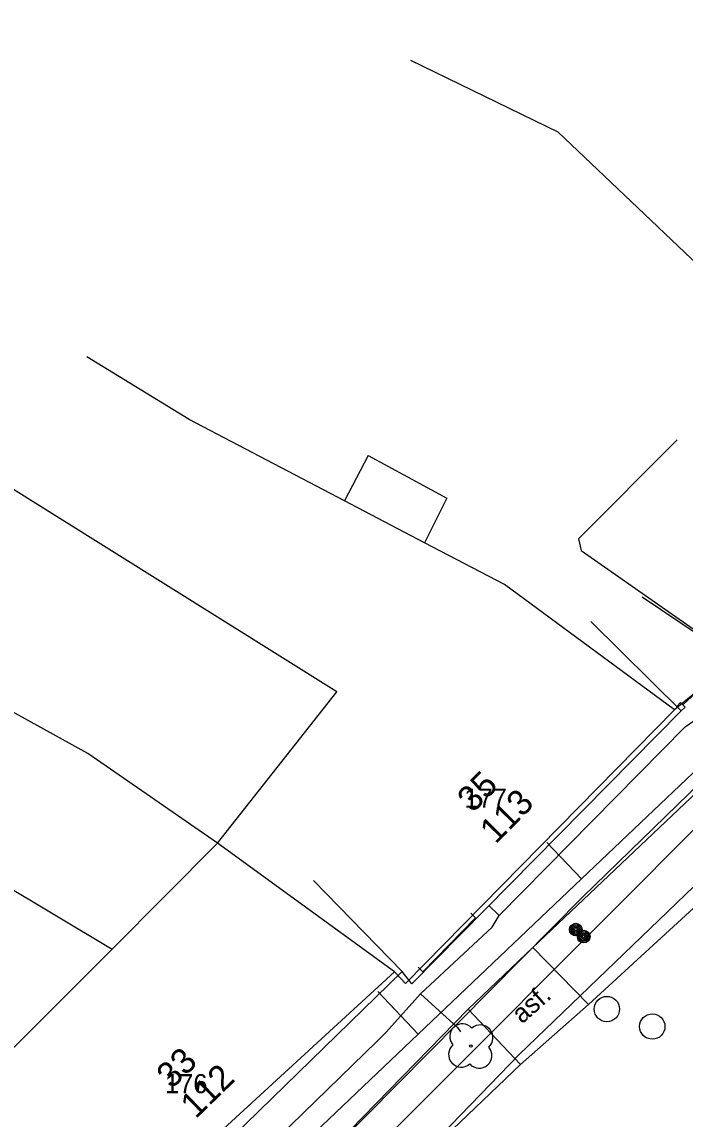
# Model space of a CAD drawing. Extents: x -601580 to 4, y -1204314 to 4.
# Drawn here: x -600403.88 to -600377.73, y -1203632.11 to -1203588.88 of the extents above; entities that cross this region are included whole.
import ezdxf

# ---------------------------------------------------------------- set-up
doc = ezdxf.new("R2010")
doc.units = 0
for name, color, linetype in [('00-INNOGY-NTL', 7, 'Continuous'), ('00-KN-HRANICE PARCEL', 7, 'Continuous'), ('00-KN-PARC. CISLA', 7, 'Continuous'), ('00-KN-VNITRNI KRESBA', 7, 'Continuous'), ('00-POLOHOPIS', 7, 'Continuous'), ('00-SITE KOM. KABEL', 7, 'Continuous'), ('00-VAK-VODA-RAD IGIS', 7, 'Continuous'), ('Vrstva 22', 7, 'Continuous'), ('Vrstva 25', 7, 'Continuous'), ('Vrstva 27', 7, 'Continuous'), ('Vrstva 6', 7, 'Continuous')]:
    doc.layers.add(name, color=color, linetype=linetype)

# ---------------------------------------------------------------- blocks, each defined once
blk = doc.blocks.new('6.01A_56')
at = {"layer": 'Vrstva 25'}
for radius in [0.25, 0.2, 0.15, 0.1, 0.05]:
    blk.add_circle((0, 0), radius, dxfattribs=at)
blk = doc.blocks.new('6.01A_58')
at = {"layer": 'Vrstva 25'}
for radius in [0.25, 0.2, 0.15, 0.1, 0.05]:
    blk.add_circle((0, 0), radius, dxfattribs=at)
blk = doc.blocks.new('6.01A_60')
at = {"layer": 'Vrstva 25'}
for radius in [0.25, 0.2, 0.15, 0.1, 0.05]:
    blk.add_circle((0, 0), radius, dxfattribs=at)
blk = doc.blocks.new('6.01A_62')
at = {"layer": 'Vrstva 25'}
for radius in [0.25, 0.2, 0.15, 0.1, 0.05]:
    blk.add_circle((0, 0), radius, dxfattribs=at)
blk = doc.blocks.new('6.20_272')
at = {"layer": 'Vrstva 27'}
blk.add_circle((0, 0), 0.5, dxfattribs=at)
blk = doc.blocks.new('6.20_274')
at = {"layer": 'Vrstva 27'}
blk.add_circle((0, 0), 0.5, dxfattribs=at)
blk = doc.blocks.new('3.13_710')
at = {"layer": 'Vrstva 22'}
blk.add_circle((0, 0), 0.05, dxfattribs=at)
for centre, start, end in [((0, 0.5), 359.9999, 179.9999), ((-0.5, 0), 89.9999, 269.9999), ((0.5, 0), 269.9999, 89.9999), ((0, -0.5), 179.9999, 359.9999)]:
    blk.add_arc(centre, 0.5, start, end, dxfattribs=at)
blk = doc.blocks.new('VCHOD_470')
at = {"layer": 'Vrstva 6'}
blk.add_line((0, 0.25), (0, 0), dxfattribs=at)
blk = doc.blocks.new('VCHOD_472')
at = {"layer": 'Vrstva 6'}
blk.add_line((0, 0.25), (0, 0), dxfattribs=at)

msp = doc.modelspace()

# ---------------------------------------------------------------- linework, layer by layer
at = {"layer": '00-INNOGY-NTL'}
for p, q in [((-600383.18, -1203621.21), (-600381.81, -1203622.65)), ((-600389.85, -1203627.09), (-600388.25, -1203628.77))]:
    msp.add_line(p, q, dxfattribs=at)
msp.add_lwpolyline([(-600244.39, -1203507.91), (-600260.95, -1203522.7), (-600267.65, -1203528.68), (-600275.18, -1203535.41), (-600281.02, -1203540.17), (-600295.58, -1203552.03), (-600296.1, -1203552.46), (-600320.53, -1203575.02), (-600330.42, -1203584.14), (-600331.17, -1203584.64), (-600349.13, -1203596.9), (-600357.35, -1203602.5), (-600360.96, -1203604.97), (-600363.47, -1203606.94), (-600365.34, -1203608.52), (-600370.83, -1203612.98), (-600376.39, -1203617.5), (-600381.81, -1203622.65), (-600388.25, -1203628.77), (-600399.65, -1203639.6)], dxfattribs=at)
at = {"layer": '00-KN-HRANICE PARCEL'}
for p, q in [((-600378.15, -1203615.98), (-600384.85, -1203611.05)), ((-600375.72, -1203613.98), (-600378.15, -1203615.98)), ((-600400.8, -1203636.96), (-600389.19, -1203626.31))]:
    msp.add_line(p, q, dxfattribs=at)
for points in [[(-600468.32, -1203708.8), (-600459.02, -1203700.91), (-600447.7, -1203689.53), (-600417.71, -1203659.51), (-600398.8, -1203640.57), (-600381.76, -1203623.36), (-600376.64, -1203618.38), (-600366.85, -1203610.56), (-600358.79, -1203604.64), (-600335.27, -1203586.75), (-600326.92, -1203580.15), (-600315.47, -1203571.41), (-600313.87, -1203569.96), (-600309.19, -1203565.44), (-600307.64, -1203563.87), (-600297.75, -1203553.71), (-600294.09, -1203550.64), (-600277.89, -1203537.3), (-600263.22, -1203524.94), (-600248.8, -1203512.9), (-600231.21, -1203497.85)], [(-600468.32, -1203708.8), (-600459.02, -1203700.91), (-600447.7, -1203689.53), (-600417.71, -1203659.51), (-600398.8, -1203640.57), (-600381.76, -1203623.36), (-600376.64, -1203618.38), (-600366.85, -1203610.56), (-600358.79, -1203604.64), (-600335.27, -1203586.75), (-600326.92, -1203580.15), (-600315.47, -1203571.41), (-600313.87, -1203569.96), (-600309.19, -1203565.44), (-600307.64, -1203563.87), (-600297.75, -1203553.71), (-600294.09, -1203550.64), (-600277.89, -1203537.3), (-600263.22, -1203524.94), (-600248.8, -1203512.9), (-600231.21, -1203497.85)], [(-600388.55, -1203590.38), (-600382.75, -1203593.21), (-600374.59, -1203600.96), (-600367.79, -1203607.52)], [(-600384.85, -1203611.05), (-600388.01, -1203609.4), (-600391.16, -1203607.75), (-600397.28, -1203604.55), (-600401.32, -1203602.08)], [(-600389.19, -1203626.31), (-600396.16, -1203621.24), (-600401.28, -1203617.71), (-600406.61, -1203614.77), (-600412.28, -1203611.63), (-600415.64, -1203609.77), (-600419.57, -1203607.57), (-600421.24, -1203606.59)], [(-600389.19, -1203626.31), (-600388.76, -1203626.77), (-600378.15, -1203615.98)]]:
    msp.add_lwpolyline(points, dxfattribs=at)
at = {"layer": '00-KN-VNITRNI KRESBA'}
for p, q in [((-600391.46, -1203615.28), (-600411.2, -1203602.94)), ((-600378.04, -1203605.35), (-600381.93, -1203609.25)), ((-600390.22, -1203605.96), (-600391.16, -1203607.75)), ((-600390.22, -1203605.96), (-600387.12, -1203607.65)), ((-600387.12, -1203607.65), (-600388.01, -1203609.4)), ((-600381.93, -1203609.25), (-600381.83, -1203609.71)), ((-600381.83, -1203609.71), (-600375.72, -1203613.98)), ((-600396.16, -1203621.24), (-600391.46, -1203615.28)), ((-600416.33, -1203615.85), (-600400.32, -1203625.42)), ((-600400.32, -1203625.42), (-600396.16, -1203621.24)), ((-600406.75, -1203631.83), (-600400.32, -1203625.42))]:
    msp.add_line(p, q, dxfattribs=at)
at = {"layer": '00-POLOHOPIS'}
for p, q in [((-600376.03, -1203614.125), (-600377.819, -1203615.79)), ((-600383.729, -1203625.347), (-600375.979, -1203617.997)), ((-600371.979, -1203618.807), (-600381.54, -1203627.597)), ((-600388.073, -1203626.304), (-600385.997, -1203624.176)), ((-600386.289, -1203627.775), (-600383.729, -1203625.347)), ((-600383.729, -1203625.347), (-600381.54, -1203627.597)), ((-600386.289, -1203627.775), (-600394.949, -1203636.66)), ((-600386.289, -1203627.775), (-600384.217, -1203629.96)), ((-600381.54, -1203627.597), (-600384.217, -1203629.96)), ((-600393.183, -1203638.488), (-600384.217, -1203629.96))]:
    msp.add_line(p, q, dxfattribs=at)
for points in [[(-600370.84, -1203603.844), (-600367.516, -1203607.579), (-600367.267, -1203607.978), (-600375.167, -1203614.412), (-600379.427, -1203611.552)], [(-600381.443, -1203612.511), (-600377.885, -1203616.024), (-600388.504, -1203626.779), (-600388.886, -1203626.29)], [(-600377.885, -1203616.024), (-600377.734, -1203615.878), (-600377.908, -1203615.698), (-600378.063, -1203615.848)], [(-600392.376, -1203622.709), (-600388.886, -1203626.29), (-600400.189, -1203637.306), (-600400.532, -1203636.909), (-600403.801, -1203633.126)]]:
    msp.add_lwpolyline(points, dxfattribs=at)
at = {"layer": '00-SITE KOM. KABEL'}
for points in [[(-600385.06, -1203624.09), (-600377.73, -1203616.65), (-600374.7, -1203614.56), (-600371.93, -1203612.56)], [(-600385.06, -1203624.09), (-600385.47, -1203623.7)], [(-600388.16, -1203627.18), (-600385.34, -1203624.55), (-600385.06, -1203624.09)], [(-600388.16, -1203627.18), (-600385.34, -1203624.55)], [(-600389.606, -1203628.776), (-600389.52, -1203628.69), (-600388.16, -1203627.18)], [(-600389.52, -1203628.69), (-600388.16, -1203627.18)], [(-600388.16, -1203627.18), (-600386.71, -1203628.5)], [(-600388.16, -1203627.18), (-600386.71, -1203628.5), (-600386.58, -1203628.67)], [(-600396.73, -1203635.32), (-600394.24, -1203633.29), (-600389.88, -1203629.05)], [(-600389.88, -1203629.05), (-600389.606, -1203628.776)]]:
    msp.add_lwpolyline(points, dxfattribs=at)
at = {"layer": '00-VAK-VODA-RAD IGIS'}
for points in [[(-600370.99, -1203614.286), (-600423.616, -1203667.016)], [(-600372.217, -1203617.987), (-600384.278, -1203629.562), (-600410.006, -1203656.146), (-600451.093, -1203698.017), (-600454.254, -1203701.013)]]:
    msp.add_lwpolyline(points, dxfattribs=at)

# ---------------------------------------------------------------- block references
at = {"layer": '00-POLOHOPIS'}
for name, p, xscale, yscale, rotation in [('VCHOD_470', (-600385.997, -1203624.176), 0.9999989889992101, 0.9999989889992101, 45.70862358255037), ('VCHOD_472', (-600388.073, -1203626.304), 0.9999989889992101, 0.9999989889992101, 45.70862358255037), ('6.20_272', (-600380.815, -1203627.777), 1.00000044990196, 1.00000044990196, 41.43505728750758), ('6.20_274', (-600379.026, -1203628.465), 1.00000044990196, 1.00000044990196, 41.43505728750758), ('3.13_710', (-600386.179, -1203629.233), 1.00000044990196, 1.00000044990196, 41.43505728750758)]:
    msp.add_blockref(name, p, dxfattribs=dict(at, xscale=xscale, yscale=yscale, rotation=rotation))
at = {"layer": '00-POLOHOPIS', "rotation": 180}
for name, p in [('6.01A_56', (-600382.039, -1203624.645)), ('6.01A_58', (-600382.039, -1203624.645)), ('6.01A_60', (-600381.728, -1203624.918)), ('6.01A_62', (-600381.728, -1203624.918))]:
    msp.add_blockref(name, p, dxfattribs=at)

# ---------------------------------------------------------------- texts
at = {"layer": '00-KN-PARC. CISLA'}
for s, p in [('177', (-600386.434, -1203619.84)), ('176', (-600398.234, -1203631.09))]:
    msp.add_text(s, height=0.75, dxfattribs=at).set_placement(p)
at = {"layer": '00-POLOHOPIS'}
for s, height, rotation, p in [('35', 1, 45.3646, (-600386.097, -1203620.071)), ('113', 1, 45.3646, (-600385.205, -1203621.304)), ('asf.', 0.75, 41.435, (-600384.163, -1203628.385)), ('33', 1, 44.2633, (-600397.97, -1203630.954)), ('112', 1, 44.2633, (-600397.026, -1203632.129))]:
    msp.add_text(s, height=height, rotation=rotation, dxfattribs=at).set_placement(p)

doc.saveas('drawing.dxf')
